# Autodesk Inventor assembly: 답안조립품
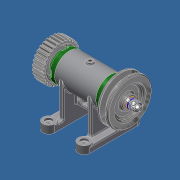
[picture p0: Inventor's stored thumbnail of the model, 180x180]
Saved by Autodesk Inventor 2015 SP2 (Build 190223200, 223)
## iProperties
Created: 2015-11
Part Number: 답안조립품
Document SubType Name: Assembly
Designer: AMC
Author: AMC
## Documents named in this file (12)
- C:\Users\AMC\Desktop\451109V1029\답안조립품.iam
- C:\Users\AMC\Desktop\451109V1029\본체.ipt
- C:\Users\AMC\Desktop\451109V1029\축.ipt
- C:\Users\AMC\Desktop\451109V1029\베어링 15 x 32 x 9.ipt
- C:\Users\AMC\Desktop\451109V1029\커버.ipt
- C:\Users\AMC\Desktop\451109V1029\오일 실 15 25 7.ipt
- C:\Users\AMC\Desktop\451109V1029\키 3 x 3 x 12.ipt
- C:\Users\AMC\Desktop\451109V1029\V벨트풀리.ipt
- C:\Users\AMC\Desktop\451109V1029\스퍼기어.ipt
- C:\Users\AMC\Desktop\451109V1029\와셔 8x17.ipt
- C:\Users\AMC\Desktop\451109V1029\스프링와셔 8.ipt
- C:\Users\AMC\Desktop\451109V1029\너트 M 8.ipt
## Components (3 placed, 2 different names)
1. KS B 2023 6002 - 15 x 32 x 9:1
2. KS B 2023 6002 - 15 x 32 x 9:2
3. V벨트풀리:1 — 각도:3
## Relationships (1: Angle 1)
- 각도:3 [Angle]: V벨트풀리:1
